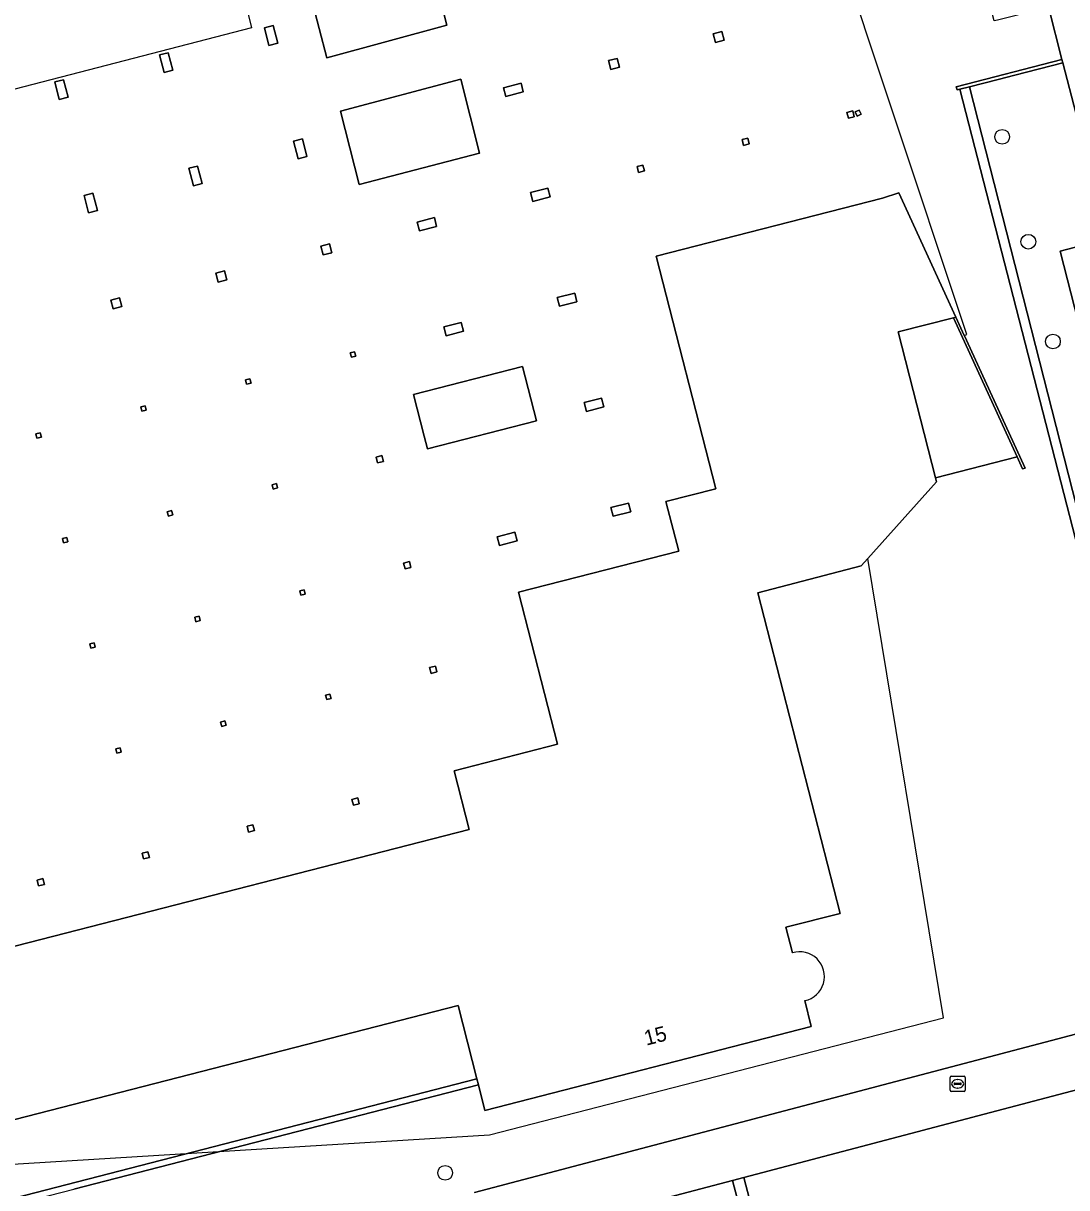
# Model space of a CAD drawing. Extents: x 160806 to 161707, y 383696 to 384148.
# Drawn here: x 161383.4 to 161452.8, y 383992.9 to 384070.3 of the extents above; entities that cross this region are included whole.
import ezdxf

# ---------------------------------------------------------------- set-up
doc = ezdxf.new("R2010")
doc.units = 0
for name, color, linetype in [('IMGEO_Berm_groen', 7, 'Continuous'), ('IMGEO_Boom', 7, 'Continuous'), ('IMGEO_Brandkraan', 7, 'Continuous'), ('IMGEO_Erf', 7, 'Continuous'), ('IMGEO_Groenvoorziening', 7, 'Continuous'), ('IMGEO_Haag', 7, 'Continuous'), ('IMGEO_Muur', 7, 'Continuous'), ('IMGEO_Pand', 7, 'Continuous'), ('IMGEO_Pand_nummerreeks', 7, 'Continuous'), ('IMGEO_Pand_overbouw', 7, 'Continuous'), ('IMGEO_Voetpad_op_trap', 7, 'Continuous'), ('IMGEO_Voetpad_open', 7, 'Continuous')]:
    doc.layers.add(name, color=color, linetype=linetype)

msp = doc.modelspace()

# ---------------------------------------------------------------- linework, layer by layer
at = {"layer": 'IMGEO_Berm_groen'}
msp.add_lwpolyline([(161456.92, 383992.48), (161455.096, 383999.898), (161431.301, 383993.631), (161433.219, 383986.347), (161435.505, 383986.955), (161440.896, 383988.302), (161447.307, 383990.003), (161448.884, 383990.399)], close=True, dxfattribs=at)
msp.add_lwpolyline([(161432.47, 383986.148), (161430.551, 383993.434), (161414.805, 383989.287)], dxfattribs=at)
at = {"layer": 'IMGEO_Boom'}
for centre in [(161448.479, 384062.779), (161450.216, 384055.807), (161451.851, 384049.177), (161411.447, 383993.933)]:
    msp.add_circle(centre, 0.489, dxfattribs=at)
at = {"layer": 'IMGEO_Brandkraan'}
for p, q in [((161445.017, 383999.422), (161445.017, 384000.274)), ((161445.092, 384000.348), (161445.944, 384000.348)), ((161446.018, 384000.274), (161446.018, 383999.422)), ((161445.276, 383999.842), (161445.276, 383999.854)), ((161445.714, 383999.805), (161445.316, 383999.805)), ((161445.319, 383999.891), (161445.717, 383999.891)), ((161445.528, 383999.568), (161445.503, 383999.568)), ((161445.505, 384000.128), (161445.53, 384000.128)), ((161445.76, 383999.854), (161445.76, 383999.842)), ((161445.944, 383999.348), (161445.092, 383999.348))]:
    msp.add_line(p, q, dxfattribs=at)
for points in [[(161445.017, 383999.422), (161445.017, 384000.274)], [(161445.092, 384000.348), (161445.944, 384000.348)], [(161446.018, 384000.274), (161446.018, 383999.422)], [(161445.944, 383999.348), (161445.092, 383999.348)]]:
    msp.add_lwpolyline(points, dxfattribs=at)
for centre, radius, start, end in [((161445.094, 384000.272), 0.0765, 91.55205, 178.44795), ((161445.094, 384000.272), 0.0765, 91.55205, 178.44795), ((161445.942, 384000.272), 0.0765, 1.55205, 88.44795), ((161445.942, 384000.272), 0.0765, 1.55205, 88.44795), ((161445.094, 383999.424), 0.0765, 181.55205, 268.44795), ((161445.094, 383999.424), 0.0765, 181.55205, 268.44795), ((161445.316, 383999.851), 0.0403, 85.87752, 175.75265), ((161445.313, 383999.841), 0.0366, 178.93798, 274.71019), ((161445.717, 383999.848), 0.043, 264.86636, 352.45326), ((161445.721, 383999.853), 0.0386, 1.73085, 96.63898), ((161445.942, 383999.424), 0.0765, 271.55205, 358.44795), ((161445.942, 383999.424), 0.0765, 271.55205, 358.44795)]:
    msp.add_arc(centre, radius, start, end, dxfattribs=at)
for centre, major_axis, ratio, start_param, end_param in [((161445.504, 383999.848), (-0.387, 0.002), 0.722429, 4.712389, 7.853982), ((161445.529, 383999.848), (-0.39, 0.002), 0.717154, 1.570796, 4.712389)]:
    msp.add_ellipse(centre, major_axis=major_axis, ratio=ratio, start_param=start_param, end_param=end_param, dxfattribs=at)
at = {"layer": 'IMGEO_Erf'}
for points in [[(161413.409, 383992.628), (161458.747, 384004.559), (161461.411, 384005.26), (161453.943, 384033.741), (161445.665, 384065.946), (161445.478, 384065.898), (161445.424, 384066.108), (161452.455, 384067.912), (161451.589, 384071.326), (161451.571, 384071.399), (161448.884, 384070.717), (161448.158, 384070.533), (161447.94, 384070.478), (161446.782, 384074.966), (161443.637, 384074.211), (161443.872, 384073.346), (161443.387, 384073.222), (161433.705, 384110.238), (161431.88, 384110.786), (161340.245, 384108.543), (161340.622, 384097.038), (161340.303, 384097.037), (161330.498, 384096.753)], [(161416.322, 384032.512), (161426.972, 384035.245), (161426.127, 384038.539), (161429.445, 384039.39), (161425.48, 384054.84), (161440.513, 384058.698), (161441.608, 384059.056), (161445.401, 384050.788), (161445.959, 384049.573), (161445.967, 384049.554), (161449.641, 384041.546), (161450.004, 384040.755), (161449.838, 384040.713), (161449.475, 384041.504), (161444.049, 384040.112), (161444.113, 384039.86), (161439.552, 384034.762), (161439.114, 384034.272), (161432.232, 384032.481), (161437.701, 384011.177), (161434.1, 384010.265), (161434.533, 384008.553)], [(161356.237, 383985.403), (161413.556, 384000.171), (161412.307, 384005.047), (161376.617, 383995.893), (161375.935, 383996.122), (161365.67, 383999.571), (161364.155, 384000.079), (161363.167, 384003.987), (161373, 384006.462), (161372.098, 384010.006), (161377.386, 384011.337), (161377.315, 384011.619), (161377.902, 384011.767), (161378.048, 384011.185), (161378.857, 384007.97), (161413.055, 384016.747), (161412.053, 384020.648), (161418.915, 384022.409), (161416.322, 384032.512)], [(161435.366, 384005.376), (161435.791, 384003.658), (161414.095, 383998.068), (161413.655, 383999.784), (161386.763, 383992.855)]]:
    msp.add_lwpolyline(points, dxfattribs=at)
for points in [[(161402.061, 384073.889), (161410.078, 384075.985), (161411.569, 384070.2), (161403.576, 384068.034)], [(161399.437, 384070.018), (161400.018, 384070.168), (161400.318, 384069.006), (161399.737, 384068.856)], [(161429.267, 384069.628), (161429.846, 384069.786), (161430.001, 384069.206), (161429.425, 384069.05)], [(161392.463, 384068.22), (161393.044, 384068.37), (161393.344, 384067.208), (161392.763, 384067.058)], [(161422.304, 384067.84), (161422.885, 384067.988), (161423.034, 384067.407), (161422.452, 384067.258)], [(161385.799, 384065.262), (161385.499, 384066.424), (161386.08, 384066.574), (161386.38, 384065.412)], [(161404.501, 384064.473), (161412.497, 384066.602), (161413.73, 384061.694), (161405.724, 384059.602)], [(161415.333, 384066.042), (161416.495, 384066.339), (161416.644, 384065.758), (161415.482, 384065.46)], [(161438.157, 384064.397), (161438.545, 384064.496), (161438.644, 384064.109), (161438.256, 384064.01)], [(161438.705, 384064.434), (161438.981, 384064.551), (161439.102, 384064.277), (161438.828, 384064.156)], [(161401.375, 384062.486), (161401.956, 384062.636), (161402.257, 384061.474), (161401.676, 384061.324)], [(161431.182, 384062.597), (161431.569, 384062.696), (161431.669, 384062.308), (161431.281, 384062.209)], [(161394.411, 384060.686), (161394.992, 384060.836), (161395.292, 384059.674), (161394.711, 384059.524)], [(161424.212, 384060.798), (161424.6, 384060.897), (161424.699, 384060.51), (161424.311, 384060.41)], [(161387.445, 384058.886), (161388.026, 384059.036), (161388.326, 384057.874), (161387.745, 384057.724)], [(161417.117, 384059.069), (161418.28, 384059.367), (161418.428, 384058.786), (161417.266, 384058.488)], [(161409.589, 384057.113), (161410.729, 384057.411), (161410.878, 384056.83), (161409.737, 384056.534)], [(161403.179, 384055.511), (161403.762, 384055.662), (161403.91, 384055.08), (161403.329, 384054.93)], [(161396.211, 384053.71), (161396.79, 384053.868), (161396.942, 384053.28), (161396.361, 384053.13)], [(161389.229, 384051.924), (161389.81, 384052.074), (161389.96, 384051.493), (161389.379, 384051.343)], [(161418.901, 384052.101), (161420.063, 384052.399), (161420.212, 384051.817), (161419.049, 384051.52)], [(161411.367, 384050.143), (161412.514, 384050.442), (161412.663, 384049.862), (161411.515, 384049.562)], [(161405.141, 384048.422), (161405.432, 384048.497), (161405.507, 384048.206), (161405.216, 384048.131)], [(161409.351, 384045.662), (161416.585, 384047.518), (161417.524, 384043.909), (161410.279, 384042.049), (161410.063, 384042.888)], [(161398.177, 384046.623), (161398.467, 384046.697), (161398.542, 384046.406), (161398.251, 384046.332)], [(161421.851, 384045.411), (161422, 384044.83), (161420.838, 384044.532), (161420.689, 384045.113)], [(161391.211, 384044.828), (161391.249, 384044.838), (161391.502, 384044.903), (161391.577, 384044.612), (161391.286, 384044.538)], [(161384.239, 384043.039), (161384.53, 384043.111), (161384.603, 384042.82), (161384.311, 384042.748)], [(161407.24, 384041.595), (161407.34, 384041.207), (161406.953, 384041.107), (161406.853, 384041.495)], [(161400.23, 384039.735), (161400.303, 384039.444), (161400.013, 384039.37), (161399.939, 384039.661)], [(161423.634, 384038.445), (161423.783, 384037.864), (161422.621, 384037.566), (161422.471, 384038.147)], [(161393.262, 384037.943), (161393.337, 384037.653), (161393.047, 384037.578), (161392.972, 384037.868)], [(161386.293, 384036.155), (161386.365, 384035.864), (161386.074, 384035.791), (161386.002, 384036.083)], [(161414.915, 384036.208), (161416.078, 384036.506), (161416.227, 384035.925), (161415.064, 384035.626)], [(161408.684, 384034.45), (161409.072, 384034.547), (161409.169, 384034.159), (161408.781, 384034.062)], [(161402.077, 384032.682), (161402.15, 384032.391), (161401.859, 384032.318), (161401.786, 384032.608)], [(161395.095, 384030.922), (161395.168, 384030.632), (161394.878, 384030.558), (161394.804, 384030.849)], [(161388.118, 384029.164), (161388.191, 384028.873), (161387.9, 384028.8), (161387.827, 384029.091)], [(161410.798, 384027.611), (161410.897, 384027.223), (161410.51, 384027.124), (161410.41, 384027.511)], [(161403.79, 384025.749), (161403.864, 384025.459), (161403.574, 384025.384), (161403.499, 384025.674)], [(161396.518, 384023.889), (161396.809, 384023.963), (161396.883, 384023.673), (161396.593, 384023.598)], [(161389.55, 384022.106), (161389.84, 384022.181), (161389.915, 384021.89), (161389.624, 384021.816)], [(161405.253, 384018.75), (161405.641, 384018.849), (161405.74, 384018.461), (161405.352, 384018.363)], [(161398.276, 384016.963), (161398.664, 384017.062), (161398.763, 384016.674), (161398.376, 384016.575)], [(161391.304, 384015.176), (161391.692, 384015.275), (161391.791, 384014.888), (161391.404, 384014.789)], [(161384.315, 384013.386), (161384.703, 384013.485), (161384.802, 384013.097), (161384.415, 384012.998)]]:
    msp.add_lwpolyline(points, close=True, dxfattribs=at)
msp.add_arc((161435.017, 384006.982), 1.644, 282.24192, 107.14221, dxfattribs=at)
at = {"layer": 'IMGEO_Groenvoorziening'}
for points in [[(161455.545, 384056.024), (161452.51, 384067.699), (161449.321, 384066.882), (161448.205, 384066.597), (161446.31, 384066.111), (161454.524, 384033.89), (161457.586, 384034.675), (161452.329, 384055.186)], [(161446.31, 384066.111), (161445.665, 384065.946), (161453.943, 384033.741), (161454.524, 384033.89)]]:
    msp.add_lwpolyline(points, close=True, dxfattribs=at)
at = {"layer": 'IMGEO_Haag'}
msp.add_lwpolyline([(161446.31, 384066.111), (161445.665, 384065.946), (161453.943, 384033.741), (161454.524, 384033.89)], close=True, dxfattribs=at)
at = {"layer": 'IMGEO_Muur'}
for points in [[(161449.321, 384066.882), (161452.51, 384067.699), (161452.455, 384067.912), (161445.424, 384066.108), (161445.478, 384065.898), (161445.665, 384065.946), (161446.31, 384066.111), (161448.205, 384066.597)], [(161445.401, 384050.788), (161445.236, 384050.746), (161449.475, 384041.504), (161449.838, 384040.713), (161450.004, 384040.755), (161449.641, 384041.546), (161445.967, 384049.554), (161445.959, 384049.573)], [(161413.655, 383999.784), (161413.556, 384000.171), (161356.237, 383985.403), (161358.404, 383976.836), (161345.931, 383973.819), (161344.245, 383980.474), (161343.993, 383980.405), (161345.704, 383973.699), (161344.695, 383973.435), (161343.942, 383973.237), (161343.999, 383973.031), (161344.653, 383973.194), (161346.051, 383973.539), (161358.462, 383976.605), (161358.596, 383976.074), (161358.982, 383976.178), (161358.21, 383979.231), (161356.722, 383985.115), (161366.613, 383987.664), (161381.829, 383991.584), (161386.763, 383992.855)]]:
    msp.add_lwpolyline(points, close=True, dxfattribs=at)
at = {"layer": 'IMGEO_Pand'}
for points in [[(161410.078, 384075.985), (161402.061, 384073.889), (161403.576, 384068.034), (161411.569, 384070.2)], [(161400.018, 384070.168), (161399.437, 384070.018), (161399.737, 384068.856), (161400.318, 384069.006)], [(161429.846, 384069.786), (161429.267, 384069.628), (161429.425, 384069.05), (161430.001, 384069.206)], [(161393.044, 384068.37), (161392.463, 384068.22), (161392.763, 384067.058), (161393.344, 384067.208)], [(161422.885, 384067.988), (161422.304, 384067.84), (161422.452, 384067.258), (161423.034, 384067.407)], [(161386.08, 384066.574), (161385.499, 384066.424), (161385.799, 384065.262), (161386.38, 384065.412)], [(161412.497, 384066.602), (161404.501, 384064.473), (161405.724, 384059.602), (161413.73, 384061.694)], [(161416.495, 384066.339), (161415.333, 384066.042), (161415.482, 384065.46), (161416.644, 384065.758)], [(161438.157, 384064.397), (161438.256, 384064.01), (161438.644, 384064.109), (161438.545, 384064.496)], [(161438.705, 384064.434), (161438.828, 384064.156), (161439.102, 384064.277), (161438.981, 384064.551)], [(161401.956, 384062.636), (161401.375, 384062.486), (161401.676, 384061.324), (161402.257, 384061.474)], [(161431.569, 384062.696), (161431.182, 384062.597), (161431.281, 384062.209), (161431.669, 384062.308)], [(161394.992, 384060.836), (161394.411, 384060.686), (161394.711, 384059.524), (161395.292, 384059.674)], [(161424.6, 384060.897), (161424.212, 384060.798), (161424.311, 384060.41), (161424.699, 384060.51)], [(161388.026, 384059.036), (161387.445, 384058.886), (161387.745, 384057.724), (161388.326, 384057.874)], [(161418.28, 384059.367), (161417.117, 384059.069), (161417.266, 384058.488), (161418.428, 384058.786)], [(161410.729, 384057.411), (161409.589, 384057.113), (161409.737, 384056.534), (161410.878, 384056.83)], [(161403.762, 384055.662), (161403.179, 384055.511), (161403.329, 384054.93), (161403.91, 384055.08)], [(161396.79, 384053.868), (161396.211, 384053.71), (161396.361, 384053.13), (161396.942, 384053.28)], [(161389.229, 384051.924), (161389.379, 384051.343), (161389.96, 384051.493), (161389.81, 384052.074)], [(161420.063, 384052.399), (161418.901, 384052.101), (161419.049, 384051.52), (161420.212, 384051.817)], [(161412.663, 384049.862), (161412.514, 384050.442), (161411.367, 384050.143), (161411.515, 384049.562)], [(161405.432, 384048.497), (161405.141, 384048.422), (161405.216, 384048.131), (161405.507, 384048.206)], [(161416.585, 384047.518), (161409.351, 384045.662), (161410.063, 384042.888), (161410.279, 384042.049), (161417.524, 384043.909)], [(161398.467, 384046.697), (161398.177, 384046.623), (161398.251, 384046.332), (161398.542, 384046.406)], [(161421.851, 384045.411), (161420.689, 384045.113), (161420.838, 384044.532), (161422, 384044.83)], [(161391.502, 384044.903), (161391.249, 384044.838), (161391.211, 384044.828), (161391.286, 384044.538), (161391.577, 384044.612)], [(161384.53, 384043.111), (161384.239, 384043.039), (161384.311, 384042.748), (161384.603, 384042.82)], [(161407.24, 384041.595), (161406.853, 384041.495), (161406.953, 384041.107), (161407.34, 384041.207)], [(161400.23, 384039.735), (161399.939, 384039.661), (161400.013, 384039.37), (161400.303, 384039.444)], [(161423.634, 384038.445), (161422.471, 384038.147), (161422.621, 384037.566), (161423.783, 384037.864)], [(161393.262, 384037.943), (161392.972, 384037.868), (161393.047, 384037.578), (161393.337, 384037.653)], [(161386.293, 384036.155), (161386.002, 384036.083), (161386.074, 384035.791), (161386.365, 384035.864)], [(161416.227, 384035.925), (161416.078, 384036.506), (161414.915, 384036.208), (161415.064, 384035.626)], [(161408.684, 384034.45), (161408.781, 384034.062), (161409.169, 384034.159), (161409.072, 384034.547)], [(161402.077, 384032.682), (161401.786, 384032.608), (161401.859, 384032.318), (161402.15, 384032.391)], [(161395.095, 384030.922), (161394.804, 384030.849), (161394.878, 384030.558), (161395.168, 384030.632)], [(161388.118, 384029.164), (161387.827, 384029.091), (161387.9, 384028.8), (161388.191, 384028.873)], [(161410.798, 384027.611), (161410.41, 384027.511), (161410.51, 384027.124), (161410.897, 384027.223)], [(161403.79, 384025.749), (161403.499, 384025.674), (161403.574, 384025.384), (161403.864, 384025.459)], [(161396.593, 384023.598), (161396.883, 384023.673), (161396.809, 384023.963), (161396.518, 384023.889)], [(161389.624, 384021.816), (161389.915, 384021.89), (161389.84, 384022.181), (161389.55, 384022.106)], [(161405.352, 384018.363), (161405.74, 384018.461), (161405.641, 384018.849), (161405.253, 384018.75)], [(161398.376, 384016.575), (161398.763, 384016.674), (161398.664, 384017.062), (161398.276, 384016.963)], [(161391.404, 384014.789), (161391.791, 384014.888), (161391.692, 384015.275), (161391.304, 384015.176)], [(161384.315, 384013.386), (161384.415, 384012.998), (161384.802, 384013.097), (161384.703, 384013.485)]]:
    msp.add_lwpolyline(points, close=True, dxfattribs=at)
for points in [[(161432.232, 384032.481), (161439.114, 384034.272), (161439.552, 384034.762), (161444.113, 384039.86), (161444.049, 384040.112), (161441.561, 384049.809), (161445.236, 384050.746), (161445.401, 384050.788), (161441.608, 384059.056), (161440.513, 384058.698), (161425.48, 384054.84), (161429.445, 384039.39), (161426.127, 384038.539), (161426.972, 384035.245), (161416.322, 384032.512), (161418.915, 384022.409), (161412.053, 384020.648), (161413.055, 384016.747), (161378.857, 384007.97)], [(161434.533, 384008.553), (161434.1, 384010.265), (161437.701, 384011.177), (161432.232, 384032.481)], [(161376.617, 383995.893), (161412.307, 384005.047), (161413.556, 384000.171), (161413.655, 383999.784), (161414.095, 383998.068), (161435.791, 384003.658), (161435.366, 384005.376)]]:
    msp.add_lwpolyline(points, dxfattribs=at)
msp.add_arc((161435.017, 384006.982), 1.644, 282.24192, 107.14221, dxfattribs=at)
at = {"layer": 'IMGEO_Pand_overbouw'}
for points in [[(161378.857, 384007.97), (161413.055, 384016.747), (161412.053, 384020.648), (161418.915, 384022.409), (161416.322, 384032.512), (161426.972, 384035.245), (161426.127, 384038.539), (161429.445, 384039.39), (161425.48, 384054.84), (161440.513, 384058.698), (161441.608, 384059.056), (161445.401, 384050.788), (161445.959, 384049.573), (161446.136, 384049.632), (161441.106, 384064.745), (161434.03, 384086.006), (161397.766, 384076.843), (161397.68, 384077.196), (161396.846, 384076.978), (161398.578, 384070.017), (161365.285, 384061.415)], [(161435.366, 384005.376), (161435.791, 384003.658), (161414.095, 383998.068), (161413.655, 383999.784), (161413.556, 384000.171), (161412.307, 384005.047), (161376.617, 383995.893), (161375.935, 383996.122), (161376.444, 383994.112), (161382.341, 383994.487), (161414.403, 383996.462), (161444.584, 384004.233), (161439.552, 384034.762), (161439.114, 384034.272), (161432.232, 384032.481), (161437.701, 384011.177), (161434.1, 384010.265), (161434.533, 384008.553)]]:
    msp.add_lwpolyline(points, dxfattribs=at)
msp.add_arc((161435.017, 384006.982), 1.644, 282.24192, 107.14221, dxfattribs=at)
at = {"layer": 'IMGEO_Voetpad_op_trap'}
msp.add_lwpolyline([(161445.236, 384050.746), (161441.561, 384049.809), (161444.049, 384040.112), (161449.475, 384041.504)], close=True, dxfattribs=at)
at = {"layer": 'IMGEO_Voetpad_open'}
for points in [[(161431.756, 384115.148), (161432.066, 384111.288), (161434.136, 384110.646), (161440.182, 384087.457), (161443.376, 384088.28), (161443.023, 384089.661), (161443.155, 384089.695), (161439.647, 384103.175), (161439.979, 384103.263), (161449.526, 384105.786), (161453.037, 384092.237), (161449.52, 384091.303), (161454.442, 384072.066), (161451.589, 384071.326), (161452.455, 384067.912), (161452.51, 384067.699), (161455.545, 384056.024), (161452.329, 384055.186), (161457.586, 384034.675), (161454.524, 384033.89), (161453.943, 384033.741), (161461.411, 384005.26), (161466.661, 384006.536), (161461.317, 384033.183)], [(161465.683, 384004.241), (161465.795, 384004.268), (161467.064, 384004.527), (161466.661, 384006.536), (161461.411, 384005.26), (161458.747, 384004.559), (161413.409, 383992.628)], [(161414.805, 383989.287), (161430.551, 383993.434), (161431.301, 383993.631), (161455.096, 383999.898), (161456.92, 383992.48), (161461.97, 383993.787), (161463.14, 383994.079)]]:
    msp.add_lwpolyline(points, dxfattribs=at)
msp.add_lwpolyline([(161431.301, 383993.631), (161430.551, 383993.434), (161432.47, 383986.148), (161433.219, 383986.347)], close=True, dxfattribs=at)

# ---------------------------------------------------------------- texts
at = {"layer": 'IMGEO_Pand_nummerreeks'}
msp.add_text('15', height=1, rotation=14.45, dxfattribs=at).set_placement((161424.821, 384002.381))

doc.saveas('drawing.dxf')
